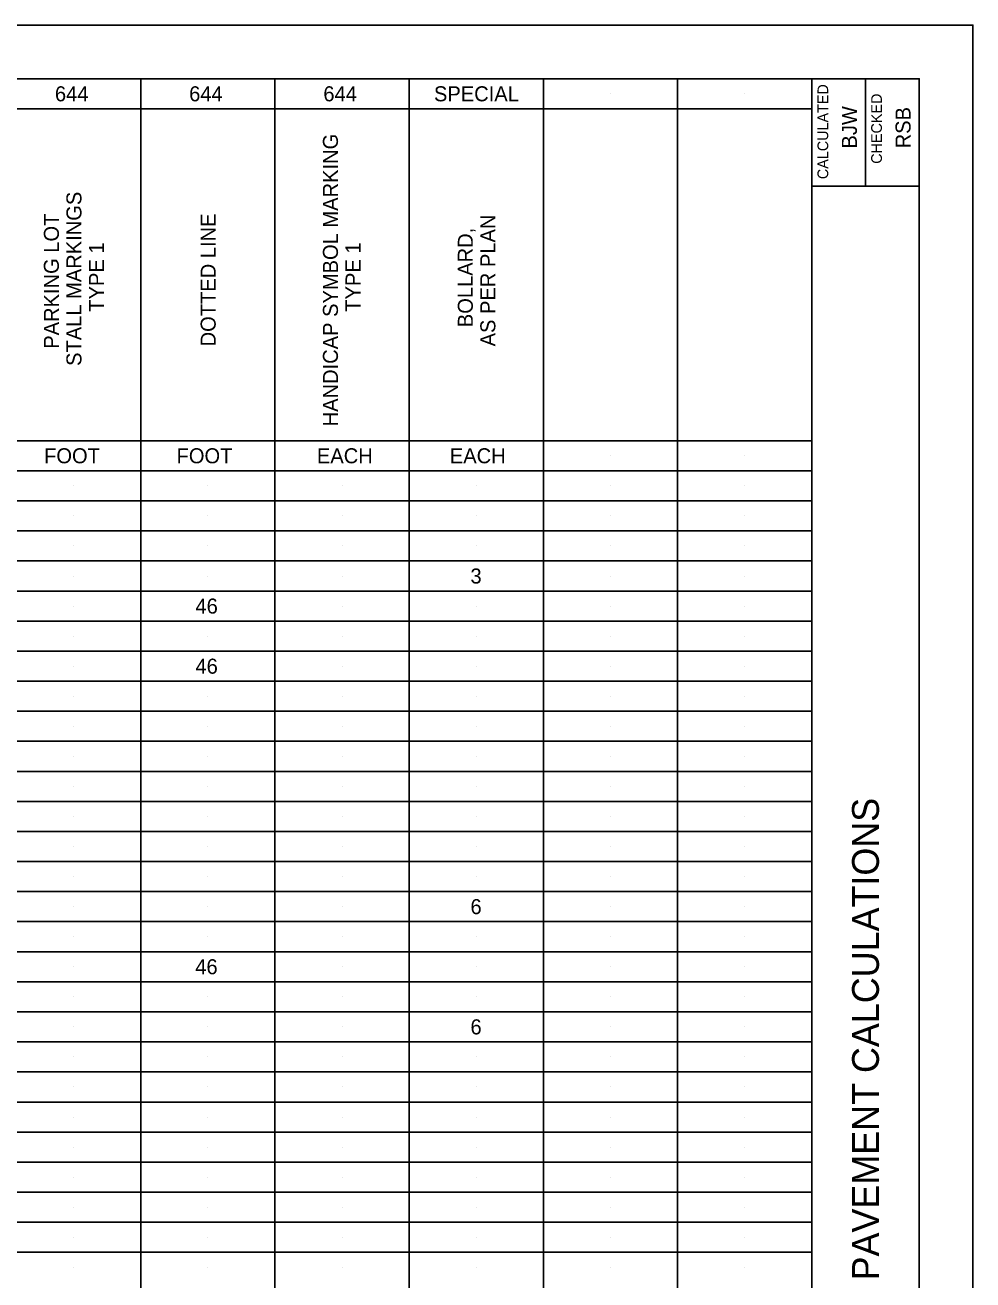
# Model space of a CAD drawing. Extents: x 2107022.8 to 2107056.8, y 706071 to 706093.
# Drawn here: x 2107047.99 to 2107056.81, y 706081.3 to 706092.99 of the extents above; entities that cross this region are included whole.
import ezdxf

# ---------------------------------------------------------------- set-up
doc = ezdxf.new("R2010")
doc.units = 0
for name, color, linetype in [('SC_Scratch1', 7, 'Continuous'), ('SH_Border', 7, 'Continuous'), ('SH_Cut_Line', 7, 'Continuous'), ('SH_Data', 7, 'Continuous'), ('SH_Text', 7, 'Continuous')]:
    doc.layers.add(name, color=color, linetype=linetype)

msp = doc.modelspace()

# ---------------------------------------------------------------- linework, layer by layer
at = {"layer": 'SC_Scratch1'}
for p, q in [((2107048.437, 706092.347), (2107048.437, 706092.347)), ((2107049.687, 706092.347), (2107049.687, 706092.347)), ((2107050.937, 706092.347), (2107050.937, 706092.347)), ((2107052.187, 706092.347), (2107052.187, 706092.347)), ((2107053.437, 706092.347), (2107053.437, 706092.347)), ((2107054.687, 706092.347), (2107054.687, 706092.347)), ((2107048.437, 706088.975), (2107048.437, 706088.975)), ((2107049.687, 706088.975), (2107049.687, 706088.975)), ((2107050.937, 706088.975), (2107050.937, 706088.975)), ((2107052.187, 706088.975), (2107052.187, 706088.975)), ((2107053.437, 706088.975), (2107053.437, 706088.975)), ((2107054.687, 706088.975), (2107054.687, 706088.975)), ((2107048.437, 706088.695), (2107048.437, 706088.695)), ((2107049.687, 706088.695), (2107049.687, 706088.695)), ((2107050.937, 706088.695), (2107050.937, 706088.695)), ((2107052.187, 706088.695), (2107052.187, 706088.695)), ((2107053.437, 706088.695), (2107053.437, 706088.695)), ((2107054.687, 706088.695), (2107054.687, 706088.695)), ((2107048.437, 706088.415), (2107048.437, 706088.415)), ((2107049.687, 706088.415), (2107049.687, 706088.415)), ((2107050.937, 706088.415), (2107050.937, 706088.415)), ((2107052.187, 706088.415), (2107052.187, 706088.415)), ((2107053.437, 706088.415), (2107053.437, 706088.415)), ((2107054.687, 706088.415), (2107054.687, 706088.415)), ((2107048.437, 706088.135), (2107048.437, 706088.135)), ((2107049.687, 706088.135), (2107049.687, 706088.135)), ((2107050.937, 706088.135), (2107050.937, 706088.135)), ((2107052.187, 706088.135), (2107052.187, 706088.135)), ((2107053.437, 706088.135), (2107053.437, 706088.135)), ((2107054.687, 706088.135), (2107054.687, 706088.135)), ((2107048.437, 706087.855), (2107048.437, 706087.855)), ((2107049.687, 706087.855), (2107049.687, 706087.855)), ((2107050.937, 706087.855), (2107050.937, 706087.855)), ((2107052.187, 706087.855), (2107052.187, 706087.855)), ((2107053.437, 706087.855), (2107053.437, 706087.855)), ((2107054.687, 706087.855), (2107054.687, 706087.855)), ((2107048.437, 706087.575), (2107048.437, 706087.575)), ((2107049.687, 706087.575), (2107049.687, 706087.575)), ((2107050.937, 706087.575), (2107050.937, 706087.575)), ((2107052.187, 706087.575), (2107052.187, 706087.575)), ((2107053.437, 706087.575), (2107053.437, 706087.575)), ((2107054.687, 706087.575), (2107054.687, 706087.575)), ((2107048.437, 706087.295), (2107048.437, 706087.295)), ((2107049.687, 706087.295), (2107049.687, 706087.295)), ((2107050.937, 706087.295), (2107050.937, 706087.295)), ((2107052.187, 706087.295), (2107052.187, 706087.295)), ((2107053.437, 706087.295), (2107053.437, 706087.295)), ((2107054.687, 706087.295), (2107054.687, 706087.295)), ((2107048.437, 706087.015), (2107048.437, 706087.015)), ((2107049.687, 706087.015), (2107049.687, 706087.015)), ((2107050.937, 706087.015), (2107050.937, 706087.015)), ((2107052.187, 706087.015), (2107052.187, 706087.015)), ((2107053.437, 706087.015), (2107053.437, 706087.015)), ((2107054.687, 706087.015), (2107054.687, 706087.015)), ((2107048.437, 706086.735), (2107048.437, 706086.735)), ((2107049.687, 706086.735), (2107049.687, 706086.735)), ((2107050.937, 706086.735), (2107050.937, 706086.735)), ((2107052.187, 706086.735), (2107052.187, 706086.735)), ((2107053.437, 706086.735), (2107053.437, 706086.735)), ((2107054.687, 706086.735), (2107054.687, 706086.735)), ((2107048.437, 706086.455), (2107048.437, 706086.455)), ((2107049.687, 706086.455), (2107049.687, 706086.455)), ((2107050.937, 706086.455), (2107050.937, 706086.455)), ((2107052.187, 706086.455), (2107052.187, 706086.455)), ((2107053.437, 706086.455), (2107053.437, 706086.455)), ((2107054.687, 706086.455), (2107054.687, 706086.455)), ((2107048.437, 706086.175), (2107048.437, 706086.175)), ((2107049.687, 706086.175), (2107049.687, 706086.175)), ((2107050.937, 706086.175), (2107050.937, 706086.175)), ((2107052.187, 706086.175), (2107052.187, 706086.175)), ((2107053.437, 706086.175), (2107053.437, 706086.175)), ((2107054.687, 706086.175), (2107054.687, 706086.175)), ((2107048.437, 706085.895), (2107048.437, 706085.895)), ((2107049.687, 706085.895), (2107049.687, 706085.895)), ((2107050.937, 706085.895), (2107050.937, 706085.895)), ((2107052.187, 706085.895), (2107052.187, 706085.895)), ((2107053.437, 706085.895), (2107053.437, 706085.895)), ((2107054.687, 706085.895), (2107054.687, 706085.895)), ((2107048.437, 706085.615), (2107048.437, 706085.615)), ((2107049.687, 706085.615), (2107049.687, 706085.615)), ((2107050.937, 706085.615), (2107050.937, 706085.615)), ((2107052.187, 706085.615), (2107052.187, 706085.615)), ((2107053.437, 706085.615), (2107053.437, 706085.615)), ((2107054.687, 706085.615), (2107054.687, 706085.615)), ((2107048.437, 706085.335), (2107048.437, 706085.335)), ((2107049.687, 706085.335), (2107049.687, 706085.335)), ((2107050.937, 706085.335), (2107050.937, 706085.335)), ((2107052.187, 706085.335), (2107052.187, 706085.335)), ((2107053.437, 706085.335), (2107053.437, 706085.335)), ((2107054.687, 706085.335), (2107054.687, 706085.335)), ((2107048.437, 706085.055), (2107048.437, 706085.055)), ((2107049.687, 706085.055), (2107049.687, 706085.055)), ((2107050.937, 706085.055), (2107050.937, 706085.055)), ((2107052.187, 706085.055), (2107052.187, 706085.055)), ((2107053.437, 706085.055), (2107053.437, 706085.055)), ((2107054.687, 706085.055), (2107054.687, 706085.055)), ((2107048.437, 706084.775), (2107048.437, 706084.775)), ((2107049.687, 706084.775), (2107049.687, 706084.775)), ((2107050.937, 706084.775), (2107050.937, 706084.775)), ((2107052.187, 706084.775), (2107052.187, 706084.775)), ((2107053.437, 706084.775), (2107053.437, 706084.775)), ((2107054.687, 706084.775), (2107054.687, 706084.775)), ((2107048.437, 706084.495), (2107048.437, 706084.495)), ((2107049.687, 706084.495), (2107049.687, 706084.495)), ((2107050.937, 706084.495), (2107050.937, 706084.495)), ((2107052.187, 706084.495), (2107052.187, 706084.495)), ((2107053.437, 706084.495), (2107053.437, 706084.495)), ((2107054.687, 706084.495), (2107054.687, 706084.495)), ((2107048.437, 706084.215), (2107048.437, 706084.215)), ((2107049.687, 706084.215), (2107049.687, 706084.215)), ((2107050.937, 706084.215), (2107050.937, 706084.215)), ((2107052.187, 706084.215), (2107052.187, 706084.215)), ((2107053.437, 706084.215), (2107053.437, 706084.215)), ((2107054.687, 706084.215), (2107054.687, 706084.215)), ((2107048.437, 706083.935), (2107048.437, 706083.935)), ((2107049.687, 706083.935), (2107049.687, 706083.935)), ((2107050.937, 706083.935), (2107050.937, 706083.935)), ((2107052.187, 706083.935), (2107052.187, 706083.935)), ((2107053.437, 706083.935), (2107053.437, 706083.935)), ((2107054.687, 706083.935), (2107054.687, 706083.935)), ((2107048.437, 706083.655), (2107048.437, 706083.655)), ((2107049.687, 706083.655), (2107049.687, 706083.655)), ((2107050.937, 706083.655), (2107050.937, 706083.655)), ((2107052.187, 706083.655), (2107052.187, 706083.655)), ((2107053.437, 706083.655), (2107053.437, 706083.655)), ((2107054.687, 706083.655), (2107054.687, 706083.655)), ((2107048.437, 706083.375), (2107048.437, 706083.375)), ((2107049.687, 706083.375), (2107049.687, 706083.375)), ((2107050.937, 706083.375), (2107050.937, 706083.375)), ((2107052.187, 706083.375), (2107052.187, 706083.375)), ((2107053.437, 706083.375), (2107053.437, 706083.375)), ((2107054.687, 706083.375), (2107054.687, 706083.375)), ((2107048.437, 706083.095), (2107048.437, 706083.095)), ((2107049.687, 706083.095), (2107049.687, 706083.095)), ((2107050.937, 706083.095), (2107050.937, 706083.095)), ((2107052.187, 706083.095), (2107052.187, 706083.095)), ((2107053.437, 706083.095), (2107053.437, 706083.095)), ((2107054.687, 706083.095), (2107054.687, 706083.095)), ((2107048.437, 706082.815), (2107048.437, 706082.815)), ((2107049.687, 706082.815), (2107049.687, 706082.815)), ((2107050.937, 706082.815), (2107050.937, 706082.815)), ((2107052.187, 706082.815), (2107052.187, 706082.815)), ((2107053.437, 706082.815), (2107053.437, 706082.815)), ((2107054.687, 706082.815), (2107054.687, 706082.815)), ((2107048.437, 706082.535), (2107048.437, 706082.535)), ((2107049.687, 706082.535), (2107049.687, 706082.535)), ((2107050.937, 706082.535), (2107050.937, 706082.535)), ((2107052.187, 706082.535), (2107052.187, 706082.535)), ((2107053.437, 706082.535), (2107053.437, 706082.535)), ((2107054.687, 706082.535), (2107054.687, 706082.535)), ((2107048.437, 706082.255), (2107048.437, 706082.255)), ((2107049.687, 706082.255), (2107049.687, 706082.255)), ((2107050.937, 706082.255), (2107050.937, 706082.255)), ((2107052.187, 706082.255), (2107052.187, 706082.255)), ((2107053.437, 706082.255), (2107053.437, 706082.255)), ((2107054.687, 706082.255), (2107054.687, 706082.255)), ((2107048.437, 706081.975), (2107048.437, 706081.975)), ((2107049.687, 706081.975), (2107049.687, 706081.975)), ((2107050.937, 706081.975), (2107050.937, 706081.975)), ((2107052.187, 706081.975), (2107052.187, 706081.975)), ((2107053.437, 706081.975), (2107053.437, 706081.975)), ((2107054.687, 706081.975), (2107054.687, 706081.975)), ((2107048.437, 706081.695), (2107048.437, 706081.695)), ((2107049.687, 706081.695), (2107049.687, 706081.695)), ((2107050.937, 706081.695), (2107050.937, 706081.695)), ((2107052.187, 706081.695), (2107052.187, 706081.695)), ((2107053.437, 706081.695), (2107053.437, 706081.695)), ((2107054.687, 706081.695), (2107054.687, 706081.695)), ((2107048.437, 706081.415), (2107048.437, 706081.415)), ((2107049.687, 706081.415), (2107049.687, 706081.415)), ((2107050.937, 706081.415), (2107050.937, 706081.415)), ((2107052.187, 706081.415), (2107052.187, 706081.415)), ((2107053.437, 706081.415), (2107053.437, 706081.415)), ((2107054.687, 706081.415), (2107054.687, 706081.415))]:
    msp.add_line(p, q, dxfattribs=at)
at = {"layer": 'SH_Border'}
for p, q in [((2107055.312, 706071.487), (2107055.312, 706092.487)), ((2107055.312, 706071.487), (2107055.312, 706092.487)), ((2107055.812, 706092.487), (2107055.812, 706091.487)), ((2107055.312, 706091.487), (2107056.312, 706091.487))]:
    msp.add_line(p, q, dxfattribs=at)
msp.add_lwpolyline([(2107024.812, 706092.487), (2107056.312, 706092.487), (2107056.312, 706071.487), (2107024.812, 706071.487)], close=True, dxfattribs=at)
at = {"layer": 'SH_Cut_Line'}
msp.add_lwpolyline([(2107022.812, 706070.987), (2107056.812, 706070.987), (2107056.812, 706092.987), (2107022.812, 706092.987)], close=True, dxfattribs=at)
at = {"layer": 'SH_Data'}
for p, q in [((2107049.062, 706071.487), (2107049.062, 706092.487)), ((2107050.312, 706071.487), (2107050.312, 706092.487)), ((2107051.562, 706071.487), (2107051.562, 706092.487)), ((2107052.812, 706071.487), (2107052.812, 706092.487)), ((2107054.062, 706071.487), (2107054.062, 706092.487)), ((2107039.062, 706092.207), (2107055.312, 706092.207)), ((2107033.062, 706089.115), (2107055.312, 706089.115)), ((2107024.812, 706088.835), (2107055.312, 706088.835)), ((2107024.812, 706088.555), (2107055.312, 706088.555)), ((2107024.812, 706088.275), (2107055.312, 706088.275)), ((2107024.812, 706087.995), (2107055.312, 706087.995)), ((2107024.812, 706087.715), (2107055.312, 706087.715)), ((2107024.812, 706087.435), (2107055.312, 706087.435)), ((2107024.812, 706087.155), (2107055.312, 706087.155)), ((2107024.812, 706086.875), (2107055.312, 706086.875)), ((2107024.812, 706086.595), (2107055.312, 706086.595)), ((2107024.812, 706086.315), (2107055.312, 706086.315)), ((2107024.812, 706086.035), (2107055.312, 706086.035)), ((2107024.812, 706085.755), (2107055.312, 706085.755)), ((2107024.812, 706085.475), (2107055.312, 706085.475)), ((2107024.812, 706085.195), (2107055.312, 706085.195)), ((2107024.812, 706084.915), (2107055.312, 706084.915)), ((2107024.812, 706084.635), (2107055.312, 706084.635)), ((2107024.812, 706084.355), (2107055.312, 706084.355)), ((2107024.812, 706084.075), (2107055.312, 706084.075)), ((2107024.812, 706083.795), (2107055.312, 706083.795)), ((2107024.812, 706083.515), (2107055.312, 706083.515)), ((2107024.812, 706083.235), (2107055.312, 706083.235)), ((2107024.812, 706082.955), (2107055.312, 706082.955)), ((2107024.812, 706082.675), (2107055.312, 706082.675)), ((2107024.812, 706082.395), (2107055.312, 706082.395)), ((2107024.812, 706082.115), (2107055.312, 706082.115)), ((2107024.812, 706081.835), (2107055.312, 706081.835)), ((2107024.812, 706081.555), (2107055.312, 706081.555))]:
    msp.add_line(p, q, dxfattribs=at)

# ---------------------------------------------------------------- texts
for s, height, p in [('CALCULATED', 0.1, (2107055.465, 706091.552)), ('CHECKED', 0.1, (2107055.965, 706091.695)), ('BJW', 0.14, (2107055.732, 706091.837)), ('RSB', 0.14, (2107056.232, 706091.839)), ('PAVEMENT CALCULATIONS', 0.25, (2107055.937, 706081.293))]:
    msp.add_text(s, height=height, rotation=90, dxfattribs=at).set_placement(p)
at = {"layer": 'SH_Text'}
for s, p in [('644', (2107048.263, 706092.277)), ('644', (2107049.513, 706092.277)), ('644', (2107050.763, 706092.277)), ('SPECIAL', (2107051.793, 706092.277)), ('FOOT', (2107048.162, 706088.905)), ('FOOT', (2107049.396, 706088.905)), ('EACH', (2107050.703, 706088.905)), ('EACH', (2107051.941, 706088.905)), ('3', (2107052.133, 706087.785)), ('46', (2107049.572, 706087.505)), ('46', (2107049.572, 706086.945)), ('6', (2107052.133, 706084.705)), ('46', (2107049.57, 706084.145)), ('6', (2107052.133, 706083.585))]:
    msp.add_text(s, height=0.14, dxfattribs=at).set_placement(p)
for s, p in [('HANDICAP SYMBOL MARKING', (2107050.899, 706089.249)), ('STALL MARKINGS', (2107048.51, 706089.812)), ('PARKING LOT', (2107048.3, 706089.972)), ('DOTTED LINE', (2107049.76, 706089.994)), ('AS PER PLAN', (2107052.365, 706089.994)), ('BOLLARD,', (2107052.155, 706090.173)), ('TYPE 1', (2107048.72, 706090.317)), ('TYPE 1', (2107051.109, 706090.317))]:
    msp.add_text(s, height=0.14, rotation=90, dxfattribs=at).set_placement(p)

doc.saveas('drawing.dxf')
